// Mitsubishi GX Works2 project: MM-15MR-8K-FE570-FX-A -220V   PLC: FX1S

PROGRAM MAIN
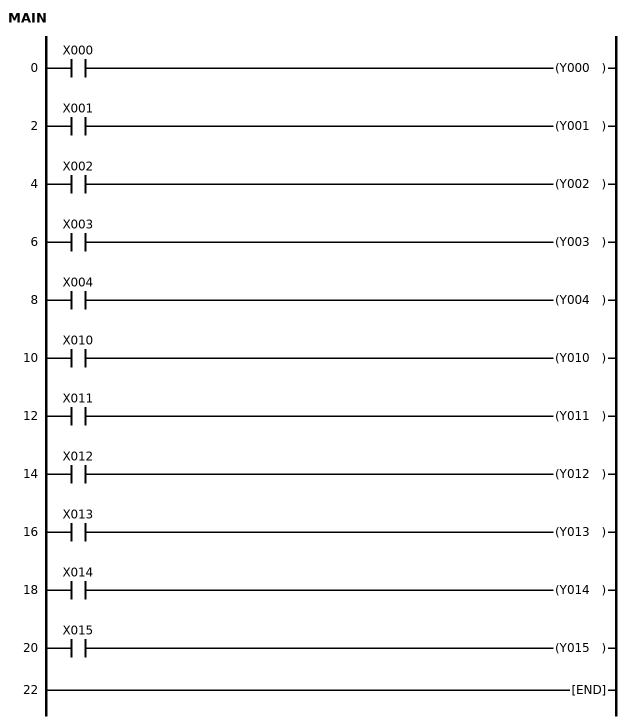
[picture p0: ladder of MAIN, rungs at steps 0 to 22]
0     LD      X000
      OUT     Y000
2     LD      X001
      OUT     Y001
4     LD      X002
      OUT     Y002
6     LD      X003
      OUT     Y003
8     LD      X004
      OUT     Y004
10    LD      X010
      OUT     Y010
12    LD      X011
      OUT     Y011
14    LD      X012
      OUT     Y012
16    LD      X013
      OUT     Y013
18    LD      X014
      OUT     Y014
20    LD      X015
      OUT     Y015
22    END
END_PROGRAM
